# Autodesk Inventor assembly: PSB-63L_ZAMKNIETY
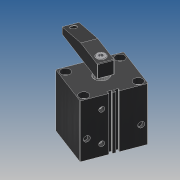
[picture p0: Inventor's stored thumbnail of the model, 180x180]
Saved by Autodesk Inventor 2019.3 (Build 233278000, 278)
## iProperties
Company: Î¢ÈíÖÐ¹ú
Created: 2013-04
Part Number: PSB-63L_ZAMKNIETY
Material: Ogólny
Description: STEP AP203
Document SubType Name: Assembly
Designer: CADENGINEERING4
Sending System: SolidWorks 2010
Preprocessor: SwSTEP 2.0
Title: PSB-L6390-1515-00.STEP
Author: Î¢ÈíÓÃ»§
Revision Number: ÈÎºÎ
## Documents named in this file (11)
- E:\SERWER_ZAPAS\Pneumatic\PSB PNEUMATIC SWING\PSB-63\PSB-63L_ZAMKNIETY.iam
- E:\SERWER_ZAPAS\Pneumatic\PSB PNEUMATIC SWING\PSB-63\PSB-L63-90-15-15-01.ipt
- E:\SERWER_ZAPAS\Pneumatic\PSB PNEUMATIC SWING\PSB-63\¸ÖÖé4.ipt
- E:\SERWER_ZAPAS\Pneumatic\PSB PNEUMATIC SWING\PSB-63\hex socket set screws with flat point gb_GB_FASTENER_SCREWS_HSFP M5X8-N.ipt
- E:\SERWER_ZAPAS\Pneumatic\PSB PNEUMATIC SWING\PSB-63\PSB-L63-90-15-15-04.ipt
- E:\SERWER_ZAPAS\Pneumatic\PSB PNEUMATIC SWING\PSB-63\PSB-L63-90-15-15-02.ipt
- E:\SERWER_ZAPAS\Pneumatic\PSB PNEUMATIC SWING\PSB-63\PSB-L63-90-15-15-05.ipt
- E:\SERWER_ZAPAS\Pneumatic\PSB PNEUMATIC SWING\PSB-63\hexagon socket head cap screws gb_GB_FASTENER_SCREWS_HSHCS M10X20-N.ipt
- E:\SERWER_ZAPAS\Pneumatic\PSB PNEUMATIC SWING\PSB-63\s¸Ë2.ipt
- E:\SERWER_ZAPAS\Pneumatic\PSB PNEUMATIC SWING\PSB-63\PSB-L63-90-15-15-03.ipt
- E:\SERWER_ZAPAS\Pneumatic\PSB PNEUMATIC SWING\PSB-63\4x40.ipt
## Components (14 placed, 14 different names)
1. PSB-L63-90-15-15-01_1 — Zestawiające:1, Zestawiające:2, Zestawiające:4, Kątowe:1
2. ¸ÖÖé4_2 — Zestawiające:10
3. hex socket set screws with flat point gb_GB_FASTENER_SCREWS_HSFP M5X8-N_3 — Zestawiające:10
4. hex socket set screws with flat point gb_GB_FASTENER_SCREWS_HSFP M5X8-N_4 — Zestawiające:12
5. PSB-L63-90-15-15-04_5 — Zestawiające:5, Równoległe:1, Zestawiające:6, Zestawiające:9, Kątowe:1
6. PSB-L63-90-15-15-02_6 — Zestawiające:3, Zestawiające:4, Zestawiające:5, Zestawiające:13, Równoległe:2
7. PSB-L63-90-15-15-05_7 — Równoległe:1, Zestawiające:6, Zestawiające:8, Zestawiające:14
8. ¸ÖÖé4_8 — Zestawiające:12
9. hexagon socket head cap screws gb_GB_FASTENER_SCREWS_HSHCS M10X20-N_9 — Zestawiające:1, Zestawiające:2, Zestawiające:3
10. s¸Ë2_10 — Zestawiające:7, Zestawiające:9
11. ¸ÖÖé4_11 — Zestawiające:11
12. PSB-L63-90-15-15-03_12 — Zestawiające:13, Równoległe:2, Zestawiające:14
13. 4x40_13 — Zestawiające:7, Zestawiające:8
14. hex socket set screws with flat point gb_GB_FASTENER_SCREWS_HSFP M5X8-N_14 — Zestawiające:11
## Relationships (17: Mate 14, Flush 2, Angle 1)
- Zestawiające:1 [Mate]: PSB-L63-90-15-15-01_1 ↔ hexagon socket head cap screws gb_GB_FASTENER_SCREWS_HSHCS M10X20-N_9
- Zestawiające:2 [Mate]: PSB-L63-90-15-15-01_1 ↔ hexagon socket head cap screws gb_GB_FASTENER_SCREWS_HSHCS M10X20-N_9
- Zestawiające:3 [Mate]: PSB-L63-90-15-15-02_6 ↔ hexagon socket head cap screws gb_GB_FASTENER_SCREWS_HSHCS M10X20-N_9
- Zestawiające:4 [Mate]: PSB-L63-90-15-15-01_1 ↔ PSB-L63-90-15-15-02_6
- Zestawiające:5 [Mate]: PSB-L63-90-15-15-04_5 ↔ PSB-L63-90-15-15-02_6
- Równoległe:1 [Flush]: PSB-L63-90-15-15-04_5 ↔ PSB-L63-90-15-15-05_7
- Zestawiające:6 [Mate]: PSB-L63-90-15-15-04_5 ↔ PSB-L63-90-15-15-05_7
- Zestawiające:7 [Mate]: s¸Ë2_10 ↔ 4x40_13
- Zestawiające:8 [Mate]: PSB-L63-90-15-15-05_7 ↔ 4x40_13
- Zestawiające:9 [Mate]: PSB-L63-90-15-15-04_5 ↔ s¸Ë2_10
- Zestawiające:10 [Mate]: ¸ÖÖé4_2 ↔ hex socket set screws with flat point gb_GB_FASTENER_SCREWS_HSFP M5X8-N_3
- Zestawiające:11 [Mate]: ¸ÖÖé4_11 ↔ hex socket set screws with flat point gb_GB_FASTENER_SCREWS_HSFP M5X8-N_14
- Zestawiające:12 [Mate]: hex socket set screws with flat point gb_GB_FASTENER_SCREWS_HSFP M5X8-N_4 ↔ ¸ÖÖé4_8
- Zestawiające:13 [Mate]: PSB-L63-90-15-15-02_6 ↔ PSB-L63-90-15-15-03_12
- Równoległe:2 [Flush]: PSB-L63-90-15-15-02_6 ↔ PSB-L63-90-15-15-03_12
- Kątowe:1 [Angle]: PSB-L63-90-15-15-01_1 ↔ PSB-L63-90-15-15-04_5
- Zestawiające:14 [Mate]: PSB-L63-90-15-15-05_7 ↔ PSB-L63-90-15-15-03_12
